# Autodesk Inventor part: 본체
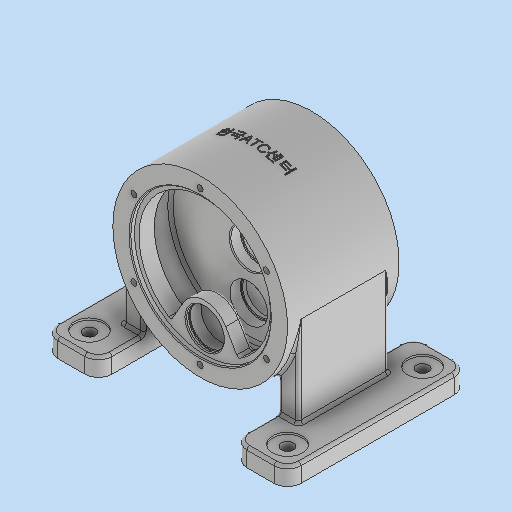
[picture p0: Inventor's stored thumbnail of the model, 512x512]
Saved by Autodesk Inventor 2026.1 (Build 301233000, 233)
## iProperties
Created: 2025-12
Part Number: 본체
Material: 일반
Document SubType Name: Modeling
Designer: PC-30
Density: 1 g/cm^3
Appearance: 기본값
Author: PC-30
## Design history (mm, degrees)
sketch "스케치1"
  geometry: L1 (-135, 100)-(-75, 100); L2 (-75, 100)-(-75, -100); L3 (-75, -100)-(-135, -100); L4 (-135, -100)-(-135, 100); L5 (-135, 100)-(-75, -100); L6 (-75, 100)-(-135, -100); 3 further points
  constraints: 12 end point, 3 midpoint, 2 parallel, 1 horizontal, 1 horizontal alignment, 1 perpendicular
  dimensions: "d0" = 200 distance from line of point (-105, -100) L1; "d1" = 60 distance between parallel lines of L2 L4; "d2" = 75 distance from line of L2 point (0, 0)
extrude "돌출1" new body sketch "스케치1" distance "d3" = 20; taper "d4" = 0 deg
sketch "스케치2"
  geometry: C1 r 97 at (0, 120); 1 further point
  constraints: 1 centre point, 1 vertical alignment
  dimensions: "d5" = 194 diameter of C1; "d6" = 120 distance of point (0, 0) C1.centre
extrude "돌출2" join sketch "스케치2" stored distance "d7" = 124; taper "d8" = 0 deg
sketch "스케치3"
  geometry: L1 (135, 20)-(75, 20) reference; L2 (97, 120)-(97, 20); L3 (75, 20)-(75, 58.486); A1 r 97 centre (0, 120) between (97, 120) and (75, 58.486) reference; 1 further point
  constraints: 4 end point, 2 point on circle, 1 parallel, 1 perpendicular, 1 point on line, 1 tangent
extrude "돌출3" join sketch "스케치3" stored distance "d9" = 100; taper "d10" = 0 deg
sketch "스케치4"
  geometry: L1 (75, 8)-(47.403, 23.933); L2 (75, 0)-(75, 20) reference; L3 (75, 0)-(135, 0) reference; C1 r 97 at (0, 120) reference; 1 further point
  constraints: 2 end point, 1 point on line
  dimensions: "d11" = 8 distance from line of L1.start L3; "d12" = 60 deg angle of L1 L2
feature "리브1" sketch "스케치4" dims "d13" = 1, "d14" = 12, "d15" = 0, "d16" = 0, "d17" = 1, "d18" = 1
sketch "스케치5"
  geometry: L1 (-62, 198)-(-57, 198); L2 (-57, 198)-(-57, 193); L3 (-57, 193)-(-40, 193); L4 (-40, 193)-(-40, 207); L5 (-40, 207)-(-8, 207); L6 (-8, 207)-(-8, 193); L7 (-8, 193)-(-8, 141); L8 (-8, 141)-(4, 141); L9 (4, 141)-(4, 139); L10 (4, 139)-(8, 139); L11 (8, 139)-(8, 207); L12 (8, 207)-(40, 207); L13 (40, 207)-(40, 193); L14 (40, 193)-(57, 193); L15 (57, 193)-(57, 198); L16 (57, 198)-(62, 198); L17 (-62, 217)-(-62, 23) reference; L18 (62, 23)-(62, 217) reference; L19 (-62, 120)-(62, 120); 10 further points
  constraints: 34 end point, 12 perpendicular, 10 midpoint, 7 point on line, 1 horizontal
  dimensions: "d19" = 156 diameter of point (-58.459, 198) L19; "d20" = 5 distance from line of L17 point (-57, 195.5); "d21" = 17 distance between parallel lines of L4 L2; "d22" = 146 diameter of L3 L19; "d23" = 174 diameter of point (-24, 207) L19; "d24" = 32 distance from line of L6 point (-40, 200); "d25" = 156 diameter of point (59.5, 198) L19; "d26" = 5 distance from line of L18 point (57, 195.5); "d27" = 146 diameter of point (48.5, 193) L19; "d28" = 17 distance of L13.end L14.end; "d29" = 32 distance between parallel lines of L13 L11; "d30" = 42 diameter of point (-2, 141) L19; "d31" = 38 diameter of point (6, 139) L19; "d32" = 66 distance between parallel lines of L9 L17
revolve "회전1" sketch "스케치5" stored, may be unused: angle "d33" = 90 deg
sketch "스케치6"
  geometry: L1 (-23.383, -39)-(-37.148, -62.842); L2 (23.383, -39)-(37.148, -62.842); L3 (0, 0)-(0, -120); A1 r 73 centre (0, 0) between (37.148, -62.842) and (-37.148, -62.842) reference; A2 r 27 centre (0, -52.5) between (23.383, -39) and (-23.383, -39)
  constraints: 6 end point, 4 point on circle, 2 tangent, 1 centre point, 1 point on line, 1 vertical
  dimensions: "d34" = 52.5 distance of L3.start A2.centre; "d35" = 54 diameter of A2; "d36" = 60 deg angle of L2 L1; "d37" = 30 deg angle of L1 L3
extrude "돌출4" join sketch "스케치6" distance "d38" = 17; taper "d39" = 0 deg
sketch "스케치7"
  geometry: L1 (-62, 42)-(-62, 198) reference; L2 (-57, 198)-(-57, 42) reference; L3 (-40, 57.158)-(-40, 81) reference; L4 (-40, 81)-(-40, 94.5) reference; L5 (-57, 88.5)-(-53.95, 88.5); L6 (-53.95, 88.5)-(-53.95, 89.75); L7 (-53.95, 89.75)-(-52, 89.75); L8 (-52, 89.75)-(-52, 88.5); L9 (-52, 88.5)-(-40, 88.5); L10 (-57, 67.5)-(-40, 67.5); 2 further points
  constraints: 12 end point, 6 point on line, 3 perpendicular, 1 horizontal, 1 midpoint, 1 parallel
  dimensions: "d40" = 52.5 distance from line of point (-62, 120) L10; "d41" = 42 diameter of L9 L10; "d42" = 44.5 diameter of L7 L10; "d43" = 12 distance between parallel lines of L8 L4; "d44" = 1.95 distance between parallel lines of L8 L6
revolve "회전2" sketch "스케치7" stored, may be unused: angle "d45" = 90 deg
sketch "스케치8"
  geometry: C1 r 21 at (0, -52.5) reference; 2 further points
  constraints: 1 coincident
hole "구멍1" sketch "스케치8" at (0, -52.5) diameter "d46" = 38; stored, may be unused: countersink angle "d50" = 90 deg, drill point angle "d52" = 118 deg; dims "d47" = 6, "d48" = 42, "d49" = 12, "d51" = 5
sketch "스케치9" dims "d53" = 170
  geometry: C1 r 97 at (0, 0) reference; 3 further points
  constraints: 2 vertical alignment, 3 other
hole "구멍2" sketch "스케치9" at (0, 85) diameter "d54" = 6.647; stored, may be unused: countersink angle "d58" = 90 deg, drill point angle "d60" = 118 deg; dims "d55" = 16, "d56" = 42, "d57" = 12, "d59" = 18
sketch "스케치10" dims "d64" = 170
  geometry: C1 r 97 at (0, 0) reference; 3 further points
  constraints: 2 vertical alignment, 3 other
hole "구멍3" sketch "스케치10" at (0, -85) diameter "d65" = 6.647; stored, may be unused: countersink angle "d69" = 90 deg, drill point angle "d71" = 118 deg; dims "d66" = 16, "d67" = 4, "d68" = 2, "d70" = 18
sketch "스케치11"
  geometry: L1 (60, -200)-(0, -200) reference; L2 (60, 0)-(60, -200) reference; 2 further points
  dimensions: "d72" = 25 distance from line of point (35, -175) L1; "d73" = 25 distance from line of point (35, -175) L2
hole "구멍4" sketch "스케치11" at (35, -175) diameter "d74" = 13.5; stored, may be unused: countersink angle "d78" = 90 deg, drill point angle "d80" = 118 deg; dims "d75" = 16, "d76" = 33, "d77" = 2, "d79" = 18
fillet "모깎기1" dims "d87" = 15
fillet "모깎기4" dims "d90" = 3
fillet "모깎기5" dims "d91" = 3
fillet "모깎기6" dims "d92" = 3
fillet "모깎기7" dims "d93" = 3
fillet "모깎기8" dims "d94" = 3
fillet "모깎기9" dims "d95" = 3
fillet "모깎기10" dims "d96" = 3
fillet "모깎기11" dims "d97" = 0.6
fillet "모깎기12" dims "d98" = 3
chamfer "모따기1" distance "d99" = 1; stored, may be unused: second distance "d100" = 2, angle "d101" = 45 deg
fillet "모깎기13" dims "d102" = 3
fillet "모깎기14" dims "d103" = 3
node "작업 평면1"
sketch "스케치12" dims "d20" = 5
  geometry: L1 (-61.5, 25)-(61.5, 25); L2 (61.5, 25)-(61.5, -25); L3 (61.5, -25)-(-61.5, -25); L4 (-61.5, -25)-(-61.5, 25); L5 (-61.5, 0)-(61.5, 0); L6 (0, -25)-(0, 25); 2 further points
  constraints: 5 midpoint, 4 end point, 1 coincident, 2 other
  dimensions: "d105" = 50 distance between parallel lines of L1 L3; "d106" = 123 distance between parallel lines of L2 L4
feature "엠보싱1" sketch "스케치12" dims "d107" = 0.5, "d108" = 0
node "솔리드1"
mirror "미러1"
mirror "미러2"
pattern_circular "원형 패턴1" dims angle "d62" = 360 deg
pattern_linear "직사각형 패턴1" dims "d86" = 220
node "투영된 루프1"
feature "A9D066F2-1C7D-4E18-AEED-F7BC21143FA4" dims "d46" = 38, "d47" = 6, "d48" = 42, "d49" = 12, "d50" = 90 deg, "d51" = 5, "d52" = 118 deg
other parameters: "d104" = 274.75
